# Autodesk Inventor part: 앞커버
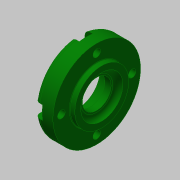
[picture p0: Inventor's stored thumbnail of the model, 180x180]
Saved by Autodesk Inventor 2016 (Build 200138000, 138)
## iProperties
Created: 2015-11
Part Number: 앞커버
Material: 알루미늄 6061
Document SubType Name: Modeling
Designer: mduedu
Density: 1 g/cm^3
Appearance: 진녹색
Author: mduedu
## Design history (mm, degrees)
sketch "스케치1"
  geometry: L1 (-7, 0)-(7, 0); L2 (-7, 0)-(-7, 26); L3 (-7, 26)-(4, 26); L4 (4, 26)-(4, 16); L5 (4, 16)-(7, 16); L6 (7, 16)-(7, 0); 2 further points
  constraints: 12 end point, 3 perpendicular, 2 parallel, 1 coincident, 1 horizontal, 1 midpoint
  dimensions: "d0" = 14 distance of L1.start L1.end; "d1" = 52 diameter of L3 L1; "d2" = 3 distance of L4.end L5.end; "d3" = 32 diameter of L5 L1
revolve "회전1" sketch "스케치1" stored, may be unused: angle "d4" = 90 deg
hole "구멍1" diameter "d7" = 25; stored, may be unused: countersink angle "d11" = 90 deg, drill point angle "d13" = 0 deg; dims "d5" = 10, "d6" = 10, "d8" = 6, "d9" = 4, "d10" = 2, "d12" = 3
hole "구멍2" diameter "d16" = 25; stored, may be unused: countersink angle "d20" = 90 deg, drill point angle "d22" = 0 deg; dims "d17" = 6, "d18" = 4, "d19" = 2, "d21" = 7.3, "d62" = 10, "d63" = 10
hole "구멍3" diameter "d25" = 17; stored, may be unused: countersink angle "d29" = 90 deg, drill point angle "d31" = 0 deg; dims "d23" = 10, "d24" = 10, "d26" = 6, "d27" = 4, "d28" = 2, "d30" = 4.2
chamfer "모따기1" distance "d32" = 0.7; stored, may be unused: second distance "d33" = 2, angle "d34" = 30 deg
fillet "모깎기1" dims "d35" = 0.3
fillet "모깎기2" dims "d36" = 3
fillet "모깎기3" dims "d37" = 3
fillet "모깎기4" dims "d38" = 0.3
sketch "스케치3" dims "d61" = 42
  geometry: C1 r 26 at (0, 0) reference; 2 further points
  constraints: 2 vertical alignment, 1 coincident, 2 other
hole "구멍4" sketch "스케치3" at (0, -21) diameter "d44" = 4.5; stored, may be unused: countersink angle "d48" = 90 deg, drill point angle "d50" = 0 deg; dims "d45" = 6, "d46" = 8, "d47" = 4.6, "d49" = 8
sketch "스케치4"
  geometry: L1 (-4, 0)-(-4, -4.69); L2 (4, 0)-(4, -4.69); A1 r 4 centre (0, 0) between (3.614, -1.714) and (-3.614, -1.714) reference; A2 r 26 centre (0, 21) between (-4, -4.69) and (4, -4.69) reference; 1 further point
  constraints: 4 end point, 4 point on circle, 2 tangent, 1 parallel, 1 vertical
extrude "돌출1" cut sketch "스케치4" stored distance "d51" = 0; taper "d52" = 0 deg
node "솔리드1"
pattern_circular "원형 패턴1" dims angle "d54" = 360 deg
